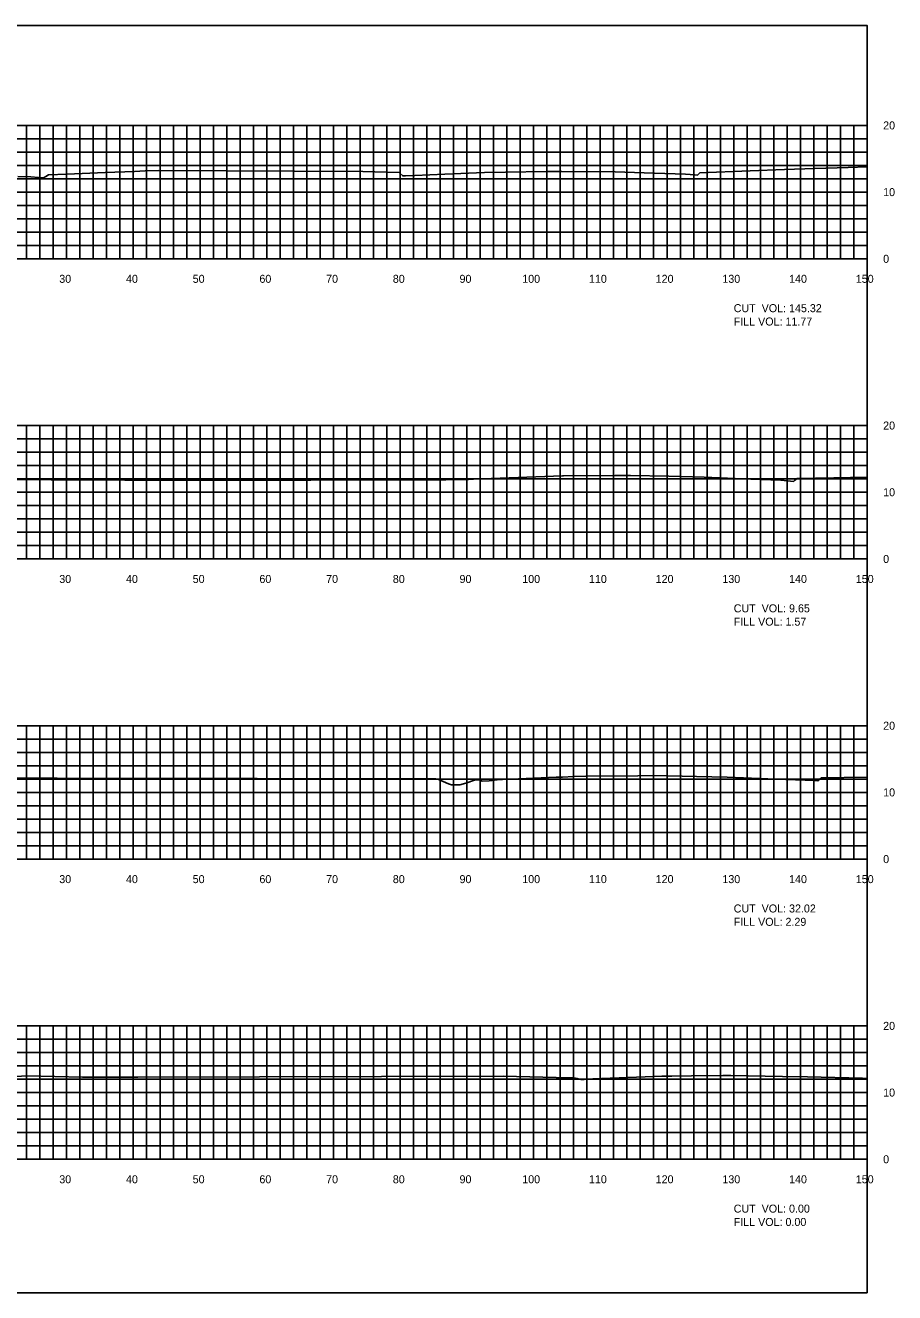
# Model space of a CAD drawing. Extents: x 1797759 to 1802785, y 249826 to 250371.
# Drawn here: x 1802314.8 to 1802445.1, y 250079.4 to 250269.4 of the extents above; entities that cross this region are included whole.
import ezdxf

# ---------------------------------------------------------------- set-up
doc = ezdxf.new("R2010")
doc.units = 0
for name, color, linetype in [('AXIS', 7, 'Continuous'), ('great seal', 7, 'Continuous'), ('Level 15', 7, 'Continuous'), ('Level 30', 7, 'Continuous'), ('Level 45', 7, 'Continuous'), ('Level 7', 7, 'Continuous'), ('LS-SURVEY POINT', 7, 'Continuous')]:
    doc.layers.add(name, color=color, linetype=linetype)

msp = doc.modelspace()

# ---------------------------------------------------------------- linework, layer by layer
at = {"layer": 'AXIS'}
msp.add_lwpolyline([(1802141, 250079.43), (1802441, 250079.43), (1802441, 250269.43), (1802141, 250269.43)], close=True, dxfattribs=at)
at = {"layer": 'great seal'}
for points in [[(1802313.71, 250246.75), (1802315.65, 250246.74), (1802316.78, 250246.64), (1802317.56, 250246.57), (1802317.9, 250246.79), (1802318.29, 250247.03), (1802321.04, 250247.14), (1802326.76, 250247.37), (1802331.2, 250247.54), (1802332.79, 250247.6), (1802334.7, 250247.67), (1802365.4, 250247.53), (1802370.83, 250247.35), (1802370.94, 250247.26), (1802371.4, 250246.86), (1802371.82, 250246.87), (1802373.2, 250246.92), (1802377.71, 250247.12), (1802383.63, 250247.36), (1802386.79, 250247.41), (1802392.95, 250247.51), (1802395.25, 250247.51), (1802403.24, 250247.49), (1802407.57, 250247.34), (1802413.77, 250247.12), (1802415.15, 250247.01), (1802415.55, 250246.98), (1802415.83, 250247.22), (1802415.93, 250247.3), (1802423.45, 250247.6), (1802428.63, 250247.81), (1802433.16, 250247.96), (1802438.15, 250248.13), (1802441, 250248.23)], [(1802307.6, 250201.33), (1802329.75, 250201.22), (1802357.61, 250201.25), (1802377.87, 250201.28), (1802379.6, 250201.33), (1802380.71, 250201.35), (1802381.23, 250201.36), (1802381.99, 250201.38), (1802395.33, 250201.88), (1802395.36, 250201.88), (1802395.37, 250201.88), (1802395.39, 250201.88), (1802395.4, 250201.88), (1802395.48, 250201.88), (1802403.19, 250201.94), (1802405.53, 250201.95), (1802411.27, 250201.83), (1802416.55, 250201.71), (1802423.56, 250201.4), (1802428.04, 250201.22), (1802428.56, 250201.18), (1802429.94, 250201.04), (1802430.11, 250201.19), (1802430.49, 250201.48), (1802436, 250201.59), (1802441, 250201.69)], [(1802311.65, 250156.56), (1802319.58, 250156.58), (1802343.05, 250156.5), (1802349.54, 250156.52), (1802372.9, 250156.49), (1802373.98, 250156.48), (1802376.33, 250156.46), (1802376.55, 250156.44), (1802376.66, 250156.42), (1802378.25, 250155.7), (1802378.71, 250155.56), (1802379.68, 250155.55), (1802379.96, 250155.58), (1802380.84, 250155.84), (1802382.15, 250156.27), (1802382.58, 250156.34), (1802382.91, 250156.32), (1802383.27, 250156.11), (1802384.34, 250156.18), (1802384.77, 250156.22), (1802385.56, 250156.3), (1802386.34, 250156.39), (1802387.05, 250156.42), (1802388.74, 250156.48), (1802394.37, 250156.7), (1802395.35, 250156.74), (1802396.99, 250156.8), (1802398.81, 250156.88), (1802406.61, 250156.93), (1802408.91, 250156.95), (1802415.42, 250156.81), (1802420.02, 250156.71), (1802427.35, 250156.43), (1802431.7, 250156.29), (1802432.16, 250156.26), (1802433.62, 250156.15), (1802433.97, 250156.46), (1802434.1, 250156.6), (1802440.95, 250156.72), (1802441, 250156.72)], [(1802310.84, 250111.71), (1802315.08, 250111.93), (1802323.4, 250111.72), (1802331.69, 250111.73), (1802386.45, 250111.91), (1802396.4, 250111.65), (1802396.73, 250111.65), (1802397.04, 250111.65), (1802397.52, 250111.56), (1802398.03, 250111.4), (1802398.07, 250111.42), (1802398.2, 250111.37), (1802398.57, 250111.4), (1802399.89, 250111.49), (1802407.73, 250111.8), (1802410.2, 250111.9), (1802411.74, 250111.91), (1802414.68, 250111.94), (1802419.35, 250111.98), (1802420.57, 250112), (1802428.33, 250111.86), (1802432.06, 250111.8), (1802440.28, 250111.58), (1802441, 250111.56)]]:
    msp.add_lwpolyline(points, dxfattribs=at)
at = {"layer": 'Level 15'}
for p, q in [((1802141, 250254.43), (1802441, 250254.43)), ((1802315, 250234.43), (1802315, 250254.43)), ((1802317, 250234.43), (1802317, 250254.43)), ((1802319, 250234.43), (1802319, 250254.43)), ((1802321, 250234.43), (1802321, 250254.43)), ((1802323, 250234.43), (1802323, 250254.43)), ((1802325, 250234.43), (1802325, 250254.43)), ((1802327, 250234.43), (1802327, 250254.43)), ((1802329, 250234.43), (1802329, 250254.43)), ((1802331, 250234.43), (1802331, 250254.43)), ((1802333, 250234.43), (1802333, 250254.43)), ((1802335, 250234.43), (1802335, 250254.43)), ((1802337, 250234.43), (1802337, 250254.43)), ((1802339, 250234.43), (1802339, 250254.43)), ((1802341, 250234.43), (1802341, 250254.43)), ((1802343, 250234.43), (1802343, 250254.43)), ((1802345, 250234.43), (1802345, 250254.43)), ((1802347, 250234.43), (1802347, 250254.43)), ((1802349, 250234.43), (1802349, 250254.43)), ((1802351, 250234.43), (1802351, 250254.43)), ((1802353, 250234.43), (1802353, 250254.43)), ((1802355, 250234.43), (1802355, 250254.43)), ((1802357, 250234.43), (1802357, 250254.43)), ((1802359, 250234.43), (1802359, 250254.43)), ((1802361, 250234.43), (1802361, 250254.43)), ((1802363, 250234.43), (1802363, 250254.43)), ((1802365, 250234.43), (1802365, 250254.43)), ((1802367, 250234.43), (1802367, 250254.43)), ((1802369, 250234.43), (1802369, 250254.43)), ((1802371, 250234.43), (1802371, 250254.43)), ((1802373, 250234.43), (1802373, 250254.43)), ((1802375, 250234.43), (1802375, 250254.43)), ((1802377, 250234.43), (1802377, 250254.43)), ((1802379, 250234.43), (1802379, 250254.43)), ((1802381, 250234.43), (1802381, 250254.43)), ((1802383, 250234.43), (1802383, 250254.43)), ((1802385, 250234.43), (1802385, 250254.43)), ((1802387, 250234.43), (1802387, 250254.43)), ((1802389, 250234.43), (1802389, 250254.43)), ((1802391, 250234.43), (1802391, 250254.43)), ((1802393, 250234.43), (1802393, 250254.43)), ((1802395, 250234.43), (1802395, 250254.43)), ((1802397, 250234.43), (1802397, 250254.43)), ((1802399, 250234.43), (1802399, 250254.43)), ((1802401, 250234.43), (1802401, 250254.43)), ((1802403, 250234.43), (1802403, 250254.43)), ((1802405, 250234.43), (1802405, 250254.43)), ((1802407, 250234.43), (1802407, 250254.43)), ((1802409, 250234.43), (1802409, 250254.43)), ((1802411, 250234.43), (1802411, 250254.43)), ((1802413, 250234.43), (1802413, 250254.43)), ((1802415, 250234.43), (1802415, 250254.43)), ((1802417, 250234.43), (1802417, 250254.43)), ((1802419, 250234.43), (1802419, 250254.43)), ((1802421, 250234.43), (1802421, 250254.43)), ((1802423, 250234.43), (1802423, 250254.43)), ((1802425, 250234.43), (1802425, 250254.43)), ((1802427, 250234.43), (1802427, 250254.43)), ((1802429, 250234.43), (1802429, 250254.43)), ((1802431, 250234.43), (1802431, 250254.43)), ((1802433, 250234.43), (1802433, 250254.43)), ((1802435, 250234.43), (1802435, 250254.43)), ((1802437, 250234.43), (1802437, 250254.43)), ((1802439, 250234.43), (1802439, 250254.43)), ((1802441, 250234.43), (1802441, 250254.43)), ((1802141, 250252.43), (1802441, 250252.43)), ((1802141, 250250.43), (1802441, 250250.43)), ((1802141, 250248.43), (1802441, 250248.43)), ((1802141, 250246.43), (1802441, 250246.43)), ((1802141, 250244.43), (1802441, 250244.43)), ((1802141, 250242.43), (1802441, 250242.43)), ((1802141, 250240.43), (1802441, 250240.43)), ((1802141, 250238.43), (1802441, 250238.43)), ((1802141, 250236.43), (1802441, 250236.43)), ((1802141, 250234.43), (1802441, 250234.43)), ((1802141, 250209.43), (1802441, 250209.43)), ((1802315, 250189.43), (1802315, 250209.43)), ((1802317, 250189.43), (1802317, 250209.43)), ((1802319, 250189.43), (1802319, 250209.43)), ((1802321, 250189.43), (1802321, 250209.43)), ((1802323, 250189.43), (1802323, 250209.43)), ((1802325, 250189.43), (1802325, 250209.43)), ((1802327, 250189.43), (1802327, 250209.43)), ((1802329, 250189.43), (1802329, 250209.43)), ((1802331, 250189.43), (1802331, 250209.43)), ((1802333, 250189.43), (1802333, 250209.43)), ((1802335, 250189.43), (1802335, 250209.43)), ((1802337, 250189.43), (1802337, 250209.43)), ((1802339, 250189.43), (1802339, 250209.43)), ((1802341, 250189.43), (1802341, 250209.43)), ((1802343, 250189.43), (1802343, 250209.43)), ((1802345, 250189.43), (1802345, 250209.43)), ((1802347, 250189.43), (1802347, 250209.43)), ((1802349, 250189.43), (1802349, 250209.43)), ((1802351, 250189.43), (1802351, 250209.43)), ((1802353, 250189.43), (1802353, 250209.43)), ((1802355, 250189.43), (1802355, 250209.43)), ((1802357, 250189.43), (1802357, 250209.43)), ((1802359, 250189.43), (1802359, 250209.43)), ((1802361, 250189.43), (1802361, 250209.43)), ((1802363, 250189.43), (1802363, 250209.43)), ((1802365, 250189.43), (1802365, 250209.43)), ((1802367, 250189.43), (1802367, 250209.43)), ((1802369, 250189.43), (1802369, 250209.43)), ((1802371, 250189.43), (1802371, 250209.43)), ((1802373, 250189.43), (1802373, 250209.43)), ((1802375, 250189.43), (1802375, 250209.43)), ((1802377, 250189.43), (1802377, 250209.43)), ((1802379, 250189.43), (1802379, 250209.43)), ((1802381, 250189.43), (1802381, 250209.43)), ((1802383, 250189.43), (1802383, 250209.43)), ((1802385, 250189.43), (1802385, 250209.43)), ((1802387, 250189.43), (1802387, 250209.43)), ((1802389, 250189.43), (1802389, 250209.43)), ((1802391, 250189.43), (1802391, 250209.43)), ((1802393, 250189.43), (1802393, 250209.43)), ((1802395, 250189.43), (1802395, 250209.43)), ((1802397, 250189.43), (1802397, 250209.43)), ((1802399, 250189.43), (1802399, 250209.43)), ((1802401, 250189.43), (1802401, 250209.43)), ((1802403, 250189.43), (1802403, 250209.43)), ((1802405, 250189.43), (1802405, 250209.43)), ((1802407, 250189.43), (1802407, 250209.43)), ((1802409, 250189.43), (1802409, 250209.43)), ((1802411, 250189.43), (1802411, 250209.43)), ((1802413, 250189.43), (1802413, 250209.43)), ((1802415, 250189.43), (1802415, 250209.43)), ((1802417, 250189.43), (1802417, 250209.43)), ((1802419, 250189.43), (1802419, 250209.43)), ((1802421, 250189.43), (1802421, 250209.43)), ((1802423, 250189.43), (1802423, 250209.43)), ((1802425, 250189.43), (1802425, 250209.43)), ((1802427, 250189.43), (1802427, 250209.43)), ((1802429, 250189.43), (1802429, 250209.43)), ((1802431, 250189.43), (1802431, 250209.43)), ((1802433, 250189.43), (1802433, 250209.43)), ((1802435, 250189.43), (1802435, 250209.43)), ((1802437, 250189.43), (1802437, 250209.43)), ((1802439, 250189.43), (1802439, 250209.43)), ((1802441, 250189.43), (1802441, 250209.43)), ((1802141, 250207.43), (1802441, 250207.43)), ((1802141, 250205.43), (1802441, 250205.43)), ((1802141, 250203.43), (1802441, 250203.43)), ((1802141, 250201.43), (1802441, 250201.43)), ((1802141, 250199.43), (1802441, 250199.43)), ((1802141, 250197.43), (1802441, 250197.43)), ((1802141, 250195.43), (1802441, 250195.43)), ((1802141, 250193.43), (1802441, 250193.43)), ((1802141, 250191.43), (1802441, 250191.43)), ((1802141, 250189.43), (1802441, 250189.43)), ((1802141, 250164.43), (1802441, 250164.43)), ((1802315, 250144.43), (1802315, 250164.43)), ((1802317, 250144.43), (1802317, 250164.43)), ((1802319, 250144.43), (1802319, 250164.43)), ((1802321, 250144.43), (1802321, 250164.43)), ((1802323, 250144.43), (1802323, 250164.43)), ((1802325, 250144.43), (1802325, 250164.43)), ((1802327, 250144.43), (1802327, 250164.43)), ((1802329, 250144.43), (1802329, 250164.43)), ((1802331, 250144.43), (1802331, 250164.43)), ((1802333, 250144.43), (1802333, 250164.43)), ((1802335, 250144.43), (1802335, 250164.43)), ((1802337, 250144.43), (1802337, 250164.43)), ((1802339, 250144.43), (1802339, 250164.43)), ((1802341, 250144.43), (1802341, 250164.43)), ((1802343, 250144.43), (1802343, 250164.43)), ((1802345, 250144.43), (1802345, 250164.43)), ((1802347, 250144.43), (1802347, 250164.43)), ((1802349, 250144.43), (1802349, 250164.43)), ((1802351, 250144.43), (1802351, 250164.43)), ((1802353, 250144.43), (1802353, 250164.43)), ((1802355, 250144.43), (1802355, 250164.43)), ((1802357, 250144.43), (1802357, 250164.43)), ((1802359, 250144.43), (1802359, 250164.43)), ((1802361, 250144.43), (1802361, 250164.43)), ((1802363, 250144.43), (1802363, 250164.43)), ((1802365, 250144.43), (1802365, 250164.43)), ((1802367, 250144.43), (1802367, 250164.43)), ((1802369, 250144.43), (1802369, 250164.43)), ((1802371, 250144.43), (1802371, 250164.43)), ((1802373, 250144.43), (1802373, 250164.43)), ((1802375, 250144.43), (1802375, 250164.43)), ((1802377, 250144.43), (1802377, 250164.43)), ((1802379, 250144.43), (1802379, 250164.43)), ((1802381, 250144.43), (1802381, 250164.43)), ((1802383, 250144.43), (1802383, 250164.43)), ((1802385, 250144.43), (1802385, 250164.43)), ((1802387, 250144.43), (1802387, 250164.43)), ((1802389, 250144.43), (1802389, 250164.43)), ((1802391, 250144.43), (1802391, 250164.43)), ((1802393, 250144.43), (1802393, 250164.43)), ((1802395, 250144.43), (1802395, 250164.43)), ((1802397, 250144.43), (1802397, 250164.43)), ((1802399, 250144.43), (1802399, 250164.43)), ((1802401, 250144.43), (1802401, 250164.43)), ((1802403, 250144.43), (1802403, 250164.43)), ((1802405, 250144.43), (1802405, 250164.43)), ((1802407, 250144.43), (1802407, 250164.43)), ((1802409, 250144.43), (1802409, 250164.43)), ((1802411, 250144.43), (1802411, 250164.43)), ((1802413, 250144.43), (1802413, 250164.43)), ((1802415, 250144.43), (1802415, 250164.43)), ((1802417, 250144.43), (1802417, 250164.43)), ((1802419, 250144.43), (1802419, 250164.43)), ((1802421, 250144.43), (1802421, 250164.43)), ((1802423, 250144.43), (1802423, 250164.43)), ((1802425, 250144.43), (1802425, 250164.43)), ((1802427, 250144.43), (1802427, 250164.43)), ((1802429, 250144.43), (1802429, 250164.43)), ((1802431, 250144.43), (1802431, 250164.43)), ((1802433, 250144.43), (1802433, 250164.43)), ((1802435, 250144.43), (1802435, 250164.43)), ((1802437, 250144.43), (1802437, 250164.43)), ((1802439, 250144.43), (1802439, 250164.43)), ((1802441, 250144.43), (1802441, 250164.43)), ((1802141, 250162.43), (1802441, 250162.43)), ((1802141, 250160.43), (1802441, 250160.43)), ((1802141, 250158.43), (1802441, 250158.43)), ((1802141, 250156.43), (1802441, 250156.43)), ((1802141, 250154.43), (1802441, 250154.43)), ((1802141, 250152.43), (1802441, 250152.43)), ((1802141, 250150.43), (1802441, 250150.43)), ((1802141, 250148.43), (1802441, 250148.43)), ((1802141, 250146.43), (1802441, 250146.43)), ((1802141, 250144.43), (1802441, 250144.43)), ((1802141, 250119.43), (1802441, 250119.43)), ((1802315, 250099.43), (1802315, 250119.43)), ((1802317, 250099.43), (1802317, 250119.43)), ((1802319, 250099.43), (1802319, 250119.43)), ((1802321, 250099.43), (1802321, 250119.43)), ((1802323, 250099.43), (1802323, 250119.43)), ((1802325, 250099.43), (1802325, 250119.43)), ((1802327, 250099.43), (1802327, 250119.43)), ((1802329, 250099.43), (1802329, 250119.43)), ((1802331, 250099.43), (1802331, 250119.43)), ((1802333, 250099.43), (1802333, 250119.43)), ((1802335, 250099.43), (1802335, 250119.43)), ((1802337, 250099.43), (1802337, 250119.43)), ((1802339, 250099.43), (1802339, 250119.43)), ((1802341, 250099.43), (1802341, 250119.43)), ((1802343, 250099.43), (1802343, 250119.43)), ((1802345, 250099.43), (1802345, 250119.43)), ((1802347, 250099.43), (1802347, 250119.43)), ((1802349, 250099.43), (1802349, 250119.43)), ((1802351, 250099.43), (1802351, 250119.43)), ((1802353, 250099.43), (1802353, 250119.43)), ((1802355, 250099.43), (1802355, 250119.43)), ((1802357, 250099.43), (1802357, 250119.43)), ((1802359, 250099.43), (1802359, 250119.43)), ((1802361, 250099.43), (1802361, 250119.43)), ((1802363, 250099.43), (1802363, 250119.43)), ((1802365, 250099.43), (1802365, 250119.43)), ((1802367, 250099.43), (1802367, 250119.43)), ((1802369, 250099.43), (1802369, 250119.43)), ((1802371, 250099.43), (1802371, 250119.43)), ((1802373, 250099.43), (1802373, 250119.43)), ((1802375, 250099.43), (1802375, 250119.43)), ((1802377, 250099.43), (1802377, 250119.43)), ((1802379, 250099.43), (1802379, 250119.43)), ((1802381, 250099.43), (1802381, 250119.43)), ((1802383, 250099.43), (1802383, 250119.43)), ((1802385, 250099.43), (1802385, 250119.43)), ((1802387, 250099.43), (1802387, 250119.43)), ((1802389, 250099.43), (1802389, 250119.43)), ((1802391, 250099.43), (1802391, 250119.43)), ((1802393, 250099.43), (1802393, 250119.43)), ((1802395, 250099.43), (1802395, 250119.43)), ((1802397, 250099.43), (1802397, 250119.43)), ((1802399, 250099.43), (1802399, 250119.43)), ((1802401, 250099.43), (1802401, 250119.43)), ((1802403, 250099.43), (1802403, 250119.43)), ((1802405, 250099.43), (1802405, 250119.43)), ((1802407, 250099.43), (1802407, 250119.43)), ((1802409, 250099.43), (1802409, 250119.43)), ((1802411, 250099.43), (1802411, 250119.43)), ((1802413, 250099.43), (1802413, 250119.43)), ((1802415, 250099.43), (1802415, 250119.43)), ((1802417, 250099.43), (1802417, 250119.43)), ((1802419, 250099.43), (1802419, 250119.43)), ((1802421, 250099.43), (1802421, 250119.43)), ((1802423, 250099.43), (1802423, 250119.43)), ((1802425, 250099.43), (1802425, 250119.43)), ((1802427, 250099.43), (1802427, 250119.43)), ((1802429, 250099.43), (1802429, 250119.43)), ((1802431, 250099.43), (1802431, 250119.43)), ((1802433, 250099.43), (1802433, 250119.43)), ((1802435, 250099.43), (1802435, 250119.43)), ((1802437, 250099.43), (1802437, 250119.43)), ((1802439, 250099.43), (1802439, 250119.43)), ((1802441, 250099.43), (1802441, 250119.43)), ((1802141, 250117.43), (1802441, 250117.43)), ((1802141, 250115.43), (1802441, 250115.43)), ((1802141, 250113.43), (1802441, 250113.43)), ((1802141, 250111.43), (1802441, 250111.43)), ((1802141, 250109.43), (1802441, 250109.43)), ((1802141, 250107.43), (1802441, 250107.43)), ((1802141, 250105.43), (1802441, 250105.43)), ((1802141, 250103.43), (1802441, 250103.43)), ((1802141, 250101.43), (1802441, 250101.43)), ((1802141, 250099.43), (1802441, 250099.43))]:
    msp.add_line(p, q, dxfattribs=at)
at = {"layer": 'Level 30'}
for p, q in [((1802441, 250234.43), (1802441, 250254.43)), ((1802441.06, 250254.43), (1802441, 250254.43)), ((1802441.06, 250244.43), (1802441, 250244.43)), ((1802141, 250234.43), (1802441, 250234.43)), ((1802321, 250234.37), (1802321, 250234.43)), ((1802331, 250234.37), (1802331, 250234.43)), ((1802341, 250234.37), (1802341, 250234.43)), ((1802351, 250234.37), (1802351, 250234.43)), ((1802361, 250234.37), (1802361, 250234.43)), ((1802371, 250234.37), (1802371, 250234.43)), ((1802381, 250234.37), (1802381, 250234.43)), ((1802391, 250234.37), (1802391, 250234.43)), ((1802401, 250234.37), (1802401, 250234.43)), ((1802411, 250234.37), (1802411, 250234.43)), ((1802421, 250234.37), (1802421, 250234.43)), ((1802431, 250234.37), (1802431, 250234.43)), ((1802441, 250234.37), (1802441, 250234.43)), ((1802441.06, 250234.43), (1802441, 250234.43)), ((1802441, 250189.43), (1802441, 250209.43)), ((1802441.06, 250209.43), (1802441, 250209.43)), ((1802441.06, 250199.43), (1802441, 250199.43)), ((1802141, 250189.43), (1802441, 250189.43)), ((1802321, 250189.37), (1802321, 250189.43)), ((1802331, 250189.37), (1802331, 250189.43)), ((1802341, 250189.37), (1802341, 250189.43)), ((1802351, 250189.37), (1802351, 250189.43)), ((1802361, 250189.37), (1802361, 250189.43)), ((1802371, 250189.37), (1802371, 250189.43)), ((1802381, 250189.37), (1802381, 250189.43)), ((1802391, 250189.37), (1802391, 250189.43)), ((1802401, 250189.37), (1802401, 250189.43)), ((1802411, 250189.37), (1802411, 250189.43)), ((1802421, 250189.37), (1802421, 250189.43)), ((1802431, 250189.37), (1802431, 250189.43)), ((1802441, 250189.37), (1802441, 250189.43)), ((1802441.06, 250189.43), (1802441, 250189.43)), ((1802441, 250144.43), (1802441, 250164.43)), ((1802441.06, 250164.43), (1802441, 250164.43)), ((1802441.06, 250154.43), (1802441, 250154.43)), ((1802141, 250144.43), (1802441, 250144.43)), ((1802321, 250144.37), (1802321, 250144.43)), ((1802331, 250144.37), (1802331, 250144.43)), ((1802341, 250144.37), (1802341, 250144.43)), ((1802351, 250144.37), (1802351, 250144.43)), ((1802361, 250144.37), (1802361, 250144.43)), ((1802371, 250144.37), (1802371, 250144.43)), ((1802381, 250144.37), (1802381, 250144.43)), ((1802391, 250144.37), (1802391, 250144.43)), ((1802401, 250144.37), (1802401, 250144.43)), ((1802411, 250144.37), (1802411, 250144.43)), ((1802421, 250144.37), (1802421, 250144.43)), ((1802431, 250144.37), (1802431, 250144.43)), ((1802441, 250144.37), (1802441, 250144.43)), ((1802441.06, 250144.43), (1802441, 250144.43)), ((1802441, 250099.43), (1802441, 250119.43)), ((1802441.06, 250119.43), (1802441, 250119.43)), ((1802441.06, 250109.43), (1802441, 250109.43)), ((1802141, 250099.43), (1802441, 250099.43)), ((1802321, 250099.37), (1802321, 250099.43)), ((1802331, 250099.37), (1802331, 250099.43)), ((1802341, 250099.37), (1802341, 250099.43)), ((1802351, 250099.37), (1802351, 250099.43)), ((1802361, 250099.37), (1802361, 250099.43)), ((1802371, 250099.37), (1802371, 250099.43)), ((1802381, 250099.37), (1802381, 250099.43)), ((1802391, 250099.37), (1802391, 250099.43)), ((1802401, 250099.37), (1802401, 250099.43)), ((1802411, 250099.37), (1802411, 250099.43)), ((1802421, 250099.37), (1802421, 250099.43)), ((1802431, 250099.37), (1802431, 250099.43)), ((1802441, 250099.37), (1802441, 250099.43)), ((1802441.06, 250099.43), (1802441, 250099.43))]:
    msp.add_line(p, q, dxfattribs=at)

# ---------------------------------------------------------------- texts
at = {"layer": 'Level 45'}
for s, p in [('30', (1802319.9, 250230.83)), ('40', (1802329.9, 250230.83)), ('50', (1802339.9, 250230.83)), ('60', (1802349.9, 250230.83)), ('70', (1802359.9, 250230.83)), ('80', (1802369.9, 250230.83)), ('90', (1802379.9, 250230.83)), ('100', (1802389.3, 250230.83)), ('110', (1802399.3, 250230.83)), ('120', (1802409.3, 250230.83)), ('130', (1802419.3, 250230.83)), ('140', (1802429.3, 250230.83)), ('150', (1802439.3, 250230.83)), ('30', (1802319.9, 250185.83)), ('40', (1802329.9, 250185.83)), ('50', (1802339.9, 250185.83)), ('60', (1802349.9, 250185.83)), ('70', (1802359.9, 250185.83)), ('80', (1802369.9, 250185.83)), ('90', (1802379.9, 250185.83)), ('100', (1802389.3, 250185.83)), ('110', (1802399.3, 250185.83)), ('120', (1802409.3, 250185.83)), ('130', (1802419.3, 250185.83)), ('140', (1802429.3, 250185.83)), ('150', (1802439.3, 250185.83)), ('30', (1802319.9, 250140.83)), ('40', (1802329.9, 250140.83)), ('50', (1802339.9, 250140.83)), ('60', (1802349.9, 250140.83)), ('70', (1802359.9, 250140.83)), ('80', (1802369.9, 250140.83)), ('90', (1802379.9, 250140.83)), ('100', (1802389.3, 250140.83)), ('110', (1802399.3, 250140.83)), ('120', (1802409.3, 250140.83)), ('130', (1802419.3, 250140.83)), ('140', (1802429.3, 250140.83)), ('150', (1802439.3, 250140.83)), ('30', (1802319.9, 250095.83)), ('40', (1802329.9, 250095.83)), ('50', (1802339.9, 250095.83)), ('60', (1802349.9, 250095.83)), ('70', (1802359.9, 250095.83)), ('80', (1802369.9, 250095.83)), ('90', (1802379.9, 250095.83)), ('100', (1802389.3, 250095.83)), ('110', (1802399.3, 250095.83)), ('120', (1802409.3, 250095.83)), ('130', (1802419.3, 250095.83)), ('140', (1802429.3, 250095.83)), ('150', (1802439.3, 250095.83))]:
    msp.add_text(s, height=1.2, dxfattribs=at).set_placement(p)
at = {"layer": 'Level 7'}
for s, p in [('20', (1802443.4, 250253.83)), ('10', (1802443.4, 250243.83)), ('0', (1802443.4, 250233.83)), ('20', (1802443.4, 250208.83)), ('10', (1802443.4, 250198.83)), ('0', (1802443.4, 250188.83)), ('20', (1802443.4, 250163.83)), ('10', (1802443.4, 250153.83)), ('0', (1802443.4, 250143.83)), ('20', (1802443.4, 250118.83)), ('10', (1802443.4, 250108.83)), ('0', (1802443.4, 250098.83))]:
    msp.add_text(s, height=1.2, dxfattribs=at).set_placement(p)
at = {"layer": 'LS-SURVEY POINT'}
for s, p in [('CUT  VOL: 145.32', (1802421, 250226.43)), ('FILL VOL: 11.77', (1802421, 250224.43)), ('CUT  VOL: 9.65', (1802421, 250181.43)), ('FILL VOL: 1.57', (1802421, 250179.43)), ('CUT  VOL: 32.02', (1802421, 250136.43)), ('FILL VOL: 2.29', (1802421, 250134.43)), ('CUT  VOL: 0.00', (1802421, 250091.43)), ('FILL VOL: 0.00', (1802421, 250089.43))]:
    msp.add_text(s, height=1.2, dxfattribs=at).set_placement(p)

doc.saveas('drawing.dxf')
